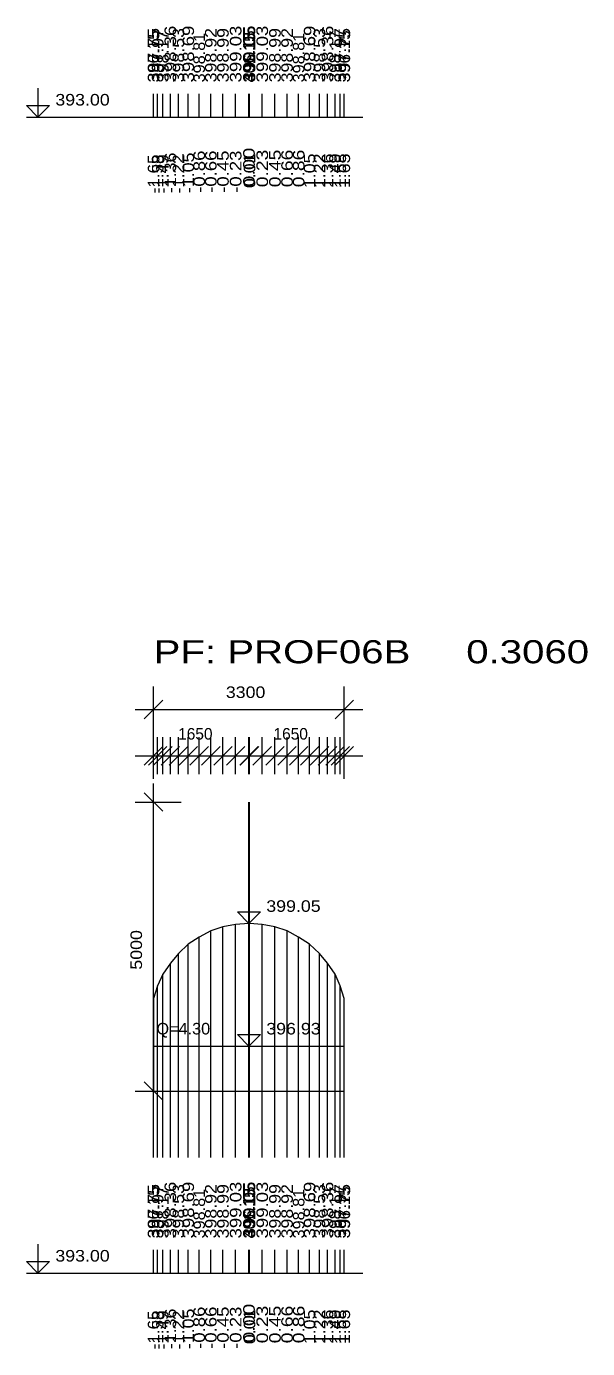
# Model space of a CAD drawing. Extents: x 7 to 442, y -393 to 441.
# Drawn here: x 418.19 to 427.9, y 59.66 to 82.53 of the extents above; entities that cross this region are included whole.
import ezdxf

# ---------------------------------------------------------------- set-up
doc = ezdxf.new("R2010")
doc.units = 0
doc.header["$LTSCALE"] = 0.08
doc.layers.add('7', color=7, linetype='Continuous', lineweight=13)

msp = doc.modelspace()

# ---------------------------------------------------------------- linework, layer by layer
at = {"layer": '7'}
for p, q in [((420.388, 80.966), (420.388, 81.366)), ((420.388, 80.966), (420.388, 81.366)), ((420.458, 80.966), (420.458, 81.366)), ((420.548, 80.966), (420.548, 81.366)), ((420.678, 80.966), (420.678, 81.366)), ((420.818, 80.966), (420.818, 81.366)), ((420.988, 80.966), (420.988, 81.366)), ((421.178, 80.966), (421.178, 81.366)), ((421.378, 80.966), (421.378, 81.366)), ((421.588, 80.966), (421.588, 81.366)), ((421.808, 80.966), (421.808, 81.366)), ((422.038, 80.966), (422.038, 81.366)), ((422.038, 80.966), (422.038, 81.366)), ((422.038, 80.966), (422.038, 81.366)), ((422.048, 80.966), (422.048, 81.366)), ((422.048, 80.966), (422.048, 81.366)), ((422.268, 80.966), (422.268, 81.366)), ((422.488, 80.966), (422.488, 81.366)), ((422.698, 80.966), (422.698, 81.366)), ((422.898, 80.966), (422.898, 81.366)), ((423.088, 80.966), (423.088, 81.366)), ((423.258, 80.966), (423.258, 81.366)), ((423.398, 80.966), (423.398, 81.366)), ((423.528, 80.966), (423.528, 81.366)), ((423.618, 80.966), (423.618, 81.366)), ((423.688, 80.966), (423.688, 81.366)), ((423.688, 80.966), (423.688, 81.366)), ((418.188, 80.966), (424.008, 80.966)), ((420.388, 69.516), (420.388, 71.116)), ((423.688, 69.516), (423.688, 71.116)), ((420.068, 70.716), (424.008, 70.716)), ((420.228, 70.556), (420.548, 70.876)), ((423.528, 70.556), (423.848, 70.876)), ((420.388, 69.596), (420.388, 70.236)), ((420.388, 69.596), (420.388, 70.236)), ((420.458, 69.596), (420.458, 70.236)), ((420.548, 69.596), (420.548, 70.236)), ((420.678, 69.596), (420.678, 70.236)), ((420.818, 69.596), (420.818, 70.236)), ((420.988, 69.596), (420.988, 70.236)), ((421.178, 69.596), (421.178, 70.236)), ((421.378, 69.596), (421.378, 70.236)), ((421.588, 69.596), (421.588, 70.236)), ((421.808, 69.596), (421.808, 70.236)), ((422.038, 69.596), (422.038, 70.236)), ((422.038, 69.596), (422.038, 70.236)), ((422.038, 69.596), (422.038, 70.236)), ((422.048, 69.596), (422.048, 70.236)), ((422.048, 69.596), (422.048, 70.236)), ((422.268, 69.596), (422.268, 70.236)), ((422.488, 69.596), (422.488, 70.236)), ((422.698, 69.596), (422.698, 70.236)), ((422.898, 69.596), (422.898, 70.236)), ((423.088, 69.596), (423.088, 70.236)), ((423.258, 69.596), (423.258, 70.236)), ((423.398, 69.596), (423.398, 70.236)), ((423.528, 69.596), (423.528, 70.236)), ((423.618, 69.596), (423.618, 70.236)), ((423.688, 69.596), (423.688, 70.236)), ((423.688, 69.596), (423.688, 70.236)), ((420.228, 69.756), (420.548, 70.076)), ((420.228, 69.756), (420.548, 70.076)), ((420.298, 69.756), (420.618, 70.076)), ((420.388, 69.756), (420.708, 70.076)), ((420.518, 69.756), (420.838, 70.076)), ((420.658, 69.756), (420.978, 70.076)), ((420.828, 69.756), (421.148, 70.076)), ((421.018, 69.756), (421.338, 70.076)), ((421.218, 69.756), (421.538, 70.076)), ((421.428, 69.756), (421.748, 70.076)), ((421.648, 69.756), (421.968, 70.076)), ((421.878, 69.756), (422.198, 70.076)), ((421.878, 69.756), (422.198, 70.076)), ((421.878, 69.756), (422.198, 70.076)), ((421.888, 69.756), (422.208, 70.076)), ((421.888, 69.756), (422.208, 70.076)), ((422.108, 69.756), (422.428, 70.076)), ((422.328, 69.756), (422.648, 70.076)), ((422.538, 69.756), (422.858, 70.076)), ((422.738, 69.756), (423.058, 70.076)), ((422.928, 69.756), (423.248, 70.076)), ((423.098, 69.756), (423.418, 70.076)), ((423.238, 69.756), (423.558, 70.076)), ((423.368, 69.756), (423.688, 70.076)), ((423.458, 69.756), (423.778, 70.076)), ((423.528, 69.756), (423.848, 70.076)), ((423.528, 69.756), (423.848, 70.076)), ((420.068, 69.916), (424.008, 69.916)), ((420.388, 63.956), (420.388, 69.436)), ((420.068, 69.116), (420.868, 69.116)), ((420.548, 68.956), (420.228, 69.276)), ((422.038, 62.966), (422.038, 69.116)), ((422.048, 62.966), (422.048, 69.116)), ((421.378, 62.966), (421.378, 66.886)), ((421.588, 62.966), (421.588, 66.956)), ((421.808, 62.966), (421.808, 66.996)), ((422.038, 62.966), (422.038, 67.016)), ((422.038, 67.016), (422.048, 67.016)), ((422.048, 62.966), (422.048, 67.016)), ((422.268, 62.966), (422.268, 66.996)), ((422.488, 62.966), (422.488, 66.956)), ((422.698, 62.966), (422.698, 66.886)), ((420.988, 62.966), (420.988, 66.656)), ((421.178, 62.966), (421.178, 66.776)), ((422.898, 62.966), (422.898, 66.776)), ((423.088, 62.966), (423.088, 66.656)), ((420.818, 62.966), (420.818, 66.496)), ((423.258, 62.966), (423.258, 66.496)), ((420.548, 62.966), (420.548, 66.136)), ((420.678, 62.966), (420.678, 66.326)), ((423.398, 62.966), (423.398, 66.326)), ((423.528, 62.966), (423.528, 66.136)), ((420.458, 62.966), (420.458, 65.936)), ((423.618, 62.966), (423.618, 65.936)), ((420.388, 62.966), (420.388, 65.716)), ((423.688, 62.966), (423.688, 65.716)), ((420.388, 64.895), (423.688, 64.895)), ((420.548, 63.956), (420.228, 64.276)), ((420.068, 64.116), (420.868, 64.116)), ((420.388, 62.966), (420.388, 64.116)), ((422.038, 62.966), (422.038, 64.116)), ((423.688, 62.966), (423.688, 64.116)), ((420.388, 60.966), (420.388, 61.366)), ((420.388, 60.966), (420.388, 61.366)), ((420.458, 60.966), (420.458, 61.366)), ((420.548, 60.966), (420.548, 61.366)), ((420.678, 60.966), (420.678, 61.366)), ((420.818, 60.966), (420.818, 61.366)), ((420.988, 60.966), (420.988, 61.366)), ((421.178, 60.966), (421.178, 61.366)), ((421.378, 60.966), (421.378, 61.366)), ((421.588, 60.966), (421.588, 61.366)), ((421.808, 60.966), (421.808, 61.366)), ((422.038, 60.966), (422.038, 61.366)), ((422.038, 60.966), (422.038, 61.366)), ((422.038, 60.966), (422.038, 61.366)), ((422.048, 60.966), (422.048, 61.366)), ((422.048, 60.966), (422.048, 61.366)), ((422.268, 60.966), (422.268, 61.366)), ((422.488, 60.966), (422.488, 61.366)), ((422.698, 60.966), (422.698, 61.366)), ((422.898, 60.966), (422.898, 61.366)), ((423.088, 60.966), (423.088, 61.366)), ((423.258, 60.966), (423.258, 61.366)), ((423.398, 60.966), (423.398, 61.366)), ((423.528, 60.966), (423.528, 61.366)), ((423.618, 60.966), (423.618, 61.366)), ((423.688, 60.966), (423.688, 61.366)), ((423.688, 60.966), (423.688, 61.366)), ((418.188, 60.966), (424.008, 60.966))]:
    msp.add_line(p, q, dxfattribs=at)
for points in [[(418.388, 81.466), (418.388, 80.966), (418.188, 81.166), (418.588, 81.166), (418.388, 80.966)], [(422.038, 69.116), (422.038, 67.016), (421.808, 66.996), (421.588, 66.956), (421.378, 66.886), (421.178, 66.776), (420.988, 66.656), (420.818, 66.496), (420.678, 66.326), (420.548, 66.136), (420.458, 65.936), (420.388, 65.716), (420.388, 64.116), (422.038, 64.116), (423.688, 64.116), (423.688, 65.716), (423.618, 65.936), (423.528, 66.136), (423.398, 66.326), (423.258, 66.496), (423.088, 66.656), (422.898, 66.776), (422.698, 66.886), (422.488, 66.956), (422.268, 66.996), (422.048, 67.016), (422.048, 69.116)], [(422.038, 67.516), (422.038, 67.016), (421.838, 67.216), (422.238, 67.216), (422.038, 67.016)], [(422.038, 65.395), (422.038, 64.895), (421.838, 65.095), (422.238, 65.095), (422.038, 64.895)], [(418.388, 61.466), (418.388, 60.966), (418.188, 61.166), (418.588, 61.166), (418.388, 60.966)]]:
    msp.add_lwpolyline(points, dxfattribs=at)

# ---------------------------------------------------------------- texts
for s, width, p in [('397.75 ', 1.15, (420.488, 81.566)), ('396.15 ', 1.1, (420.488, 81.566)), ('397.97 ', 1.15, (420.558, 81.566)), ('398.17 ', 1.1, (420.648, 81.566)), ('398.36 ', 1.2, (420.778, 81.566)), ('398.53 ', 1.15, (420.918, 81.566)), ('398.69 ', 1.2, (421.088, 81.566)), ('398.81 ', 1.05, (421.278, 81.566)), ('398.92 ', 1.15, (421.478, 81.566)), ('398.99 ', 1.15, (421.688, 81.566)), ('399.03 ', 1.2, (421.908, 81.566)), ('399.05 ', 1.2, (422.138, 81.566)), ('396.15 ', 1.1, (422.138, 81.566)), ('401.15 ', 1.05, (422.138, 81.566)), ('399.05 ', 1.2, (422.148, 81.566)), ('401.15 ', 1.05, (422.148, 81.566)), ('399.03 ', 1.2, (422.368, 81.566)), ('398.99 ', 1.15, (422.588, 81.566)), ('398.92 ', 1.15, (422.798, 81.566)), ('398.81 ', 1.05, (422.998, 81.566)), ('398.69 ', 1.2, (423.188, 81.566)), ('398.53 ', 1.15, (423.358, 81.566)), ('398.36 ', 1.2, (423.498, 81.566)), ('398.17 ', 1.1, (423.628, 81.566)), ('397.97 ', 1.15, (423.718, 81.566)), ('397.75 ', 1.15, (423.788, 81.566)), ('396.15 ', 1.1, (423.788, 81.566)), (' -1.65 ', 1.1, (420.488, 79.566)), (' -1.65 ', 1.1, (420.488, 79.566)), (' -1.58 ', 1.1, (420.558, 79.566)), (' -1.49 ', 1.1, (420.648, 79.566)), (' -1.36 ', 1.15, (420.778, 79.566)), (' -1.22 ', 1.1, (420.918, 79.566)), (' -1.05 ', 1.15, (421.088, 79.566)), (' -0.86 ', 1.2, (421.278, 79.566)), (' -0.66 ', 1.2, (421.478, 79.566)), (' -0.45 ', 1.2, (421.688, 79.566)), (' -0.23 ', 1.2, (421.908, 79.566)), ('  0.00 ', 1.3, (422.138, 79.566)), ('  0.00 ', 1.3, (422.138, 79.566)), ('  0.00 ', 1.3, (422.138, 79.566)), ('  0.01 ', 1.15, (422.148, 79.566)), ('  0.01 ', 1.15, (422.148, 79.566)), ('  0.23 ', 1.25, (422.368, 79.566)), ('  0.45 ', 1.25, (422.588, 79.566)), ('  0.66 ', 1.25, (422.798, 79.566)), ('  0.86 ', 1.25, (422.998, 79.566)), ('  1.05 ', 1.15, (423.188, 79.566)), ('  1.22 ', 1.15, (423.358, 79.566)), ('  1.36 ', 1.15, (423.498, 79.566)), ('  1.49 ', 1.15, (423.628, 79.566)), ('  1.58 ', 1.15, (423.718, 79.566)), ('  1.65 ', 1.15, (423.788, 79.566)), ('  1.65 ', 1.15, (423.788, 79.566)), ('5000', 1.15, (420.188, 66.216)), ('397.75 ', 1.15, (420.488, 61.566)), ('396.15 ', 1.1, (420.488, 61.566)), ('397.97 ', 1.15, (420.558, 61.566)), ('398.17 ', 1.1, (420.648, 61.566)), ('398.36 ', 1.2, (420.778, 61.566)), ('398.53 ', 1.15, (420.918, 61.566)), ('398.69 ', 1.2, (421.088, 61.566)), ('398.92 ', 1.15, (421.478, 61.566)), ('398.99 ', 1.15, (421.688, 61.566)), ('399.03 ', 1.2, (421.908, 61.566)), ('399.05 ', 1.2, (422.138, 61.566)), ('396.15 ', 1.1, (422.138, 61.566)), ('399.05 ', 1.2, (422.148, 61.566)), ('399.03 ', 1.2, (422.368, 61.566)), ('398.99 ', 1.15, (422.588, 61.566)), ('398.92 ', 1.15, (422.798, 61.566)), ('398.69 ', 1.2, (423.188, 61.566)), ('398.53 ', 1.15, (423.358, 61.566)), ('398.36 ', 1.2, (423.498, 61.566)), ('398.17 ', 1.1, (423.628, 61.566)), ('397.97 ', 1.15, (423.718, 61.566)), ('397.75 ', 1.15, (423.788, 61.566)), ('396.15 ', 1.1, (423.788, 61.566)), ('398.81 ', 1.05, (421.278, 61.566)), ('401.15 ', 1.05, (422.138, 61.566)), ('401.15 ', 1.05, (422.148, 61.566)), ('398.81 ', 1.05, (422.998, 61.566)), ('  0.00 ', 1.3, (422.138, 59.566)), ('  0.00 ', 1.3, (422.138, 59.566)), ('  0.00 ', 1.3, (422.138, 59.566)), ('  0.23 ', 1.25, (422.368, 59.566)), ('  0.45 ', 1.25, (422.588, 59.566)), ('  0.66 ', 1.25, (422.798, 59.566)), ('  0.86 ', 1.25, (422.998, 59.566)), (' -1.65 ', 1.1, (420.488, 59.566)), (' -1.65 ', 1.1, (420.488, 59.566)), (' -1.58 ', 1.1, (420.558, 59.566)), (' -1.49 ', 1.1, (420.648, 59.566)), (' -1.36 ', 1.15, (420.778, 59.566)), (' -1.22 ', 1.1, (420.918, 59.566)), (' -1.05 ', 1.15, (421.088, 59.566)), (' -0.86 ', 1.2, (421.278, 59.566)), (' -0.66 ', 1.2, (421.478, 59.566)), (' -0.45 ', 1.2, (421.688, 59.566)), (' -0.23 ', 1.2, (421.908, 59.566)), ('  0.01 ', 1.15, (422.148, 59.566)), ('  0.01 ', 1.15, (422.148, 59.566)), ('  1.05 ', 1.15, (423.188, 59.566)), ('  1.22 ', 1.15, (423.358, 59.566)), ('  1.36 ', 1.15, (423.498, 59.566)), ('  1.49 ', 1.15, (423.628, 59.566)), ('  1.58 ', 1.15, (423.718, 59.566)), ('  1.65 ', 1.15, (423.788, 59.566)), ('  1.65 ', 1.15, (423.788, 59.566))]:
    msp.add_text(s, height=0.2, rotation=90, dxfattribs=dict(at, width=width)).set_placement(p)
for s, height, width, p in [('393.00', 0.2, 1.15, (418.688, 81.166)), ('PF: PROF06B     0.3060', 0.4, 1.3, (420.388, 71.516)), ('3300', 0.2, 1.15, (421.638, 70.916)), ('399.05', 0.2, 1.15, (422.338, 67.216)), ('Q=4.30', 0.2, 1.05, (420.438, 65.095)), ('396.93', 0.2, 1.15, (422.338, 65.095)), ('393.00', 0.2, 1.15, (418.688, 61.166))]:
    msp.add_text(s, height=height, dxfattribs=dict(at, width=width)).set_placement(p)
for p in [(420.813, 70.196), (422.463, 70.196)]:
    msp.add_text('1650', height=0.2, dxfattribs=at).set_placement(p)

doc.saveas('drawing.dxf')
